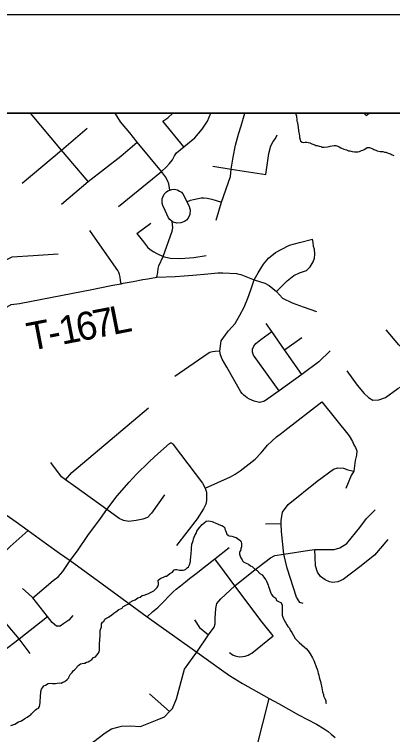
# Model space of a CAD drawing. Extents: x 0 to 34, y 0 to 22.
# Drawn here: x 7.879 to 8.261, y 20.27 to 21 of the extents above; entities that cross this region are included whole.
import ezdxf

# ---------------------------------------------------------------- set-up
doc = ezdxf.new("R2010")
doc.units = 0
for name, color, linetype in [('GM_X_Corporation', 7, 'Continuous'), ('GM_X_County_Road', 7, 'Continuous'), ('GM_X_Minor_River', 7, 'Continuous'), ('GM_X_Township_Road', 7, 'Continuous'), ('GM_X_Township_Road_Text', 7, 'Continuous'), ('SH_Cut_Line', 7, 'Continuous'), ('SH_Data', 7, 'Continuous')]:
    doc.layers.add(name, color=color, linetype=linetype)

msp = doc.modelspace()

# ---------------------------------------------------------------- linework, layer by layer
at = {"layer": 'GM_X_Corporation'}
msp.add_lwpolyline([(8.26616, 20.9), (5.67696, 20.9)], dxfattribs=at)
at = {"layer": 'GM_X_County_Road'}
msp.add_lwpolyline([(7.85884, 20.50097), (7.88029, 20.48584), (7.89246, 20.47726), (7.9113, 20.46371), (7.92425, 20.45427), (7.93502, 20.44671), (7.9675, 20.42329), (8.01317, 20.38987), (8.02704, 20.37972), (8.04097, 20.3698), (8.06328, 20.35377), (8.07499, 20.34548), (8.08822, 20.33608), (8.09625, 20.33039), (8.10945, 20.3222), (8.13664, 20.30712), (8.14579, 20.30199), (8.16632, 20.29058), (8.18434, 20.28088), (8.19201, 20.27643), (8.1961, 20.27351), (8.1994, 20.27098), (8.20326, 20.26735)], dxfattribs=at)
at = {"layer": 'GM_X_Minor_River'}
for points in [[(8.16322, 20.9), (8.16404, 20.89707), (8.16401, 20.89593), (8.16453, 20.89383), (8.16448, 20.89193), (8.16501, 20.8904), (8.1655, 20.88736), (8.16584, 20.88564), (8.16632, 20.88221), (8.16666, 20.8805), (8.16681, 20.87916), (8.16713, 20.87669), (8.16728, 20.87517), (8.16779, 20.87307), (8.16814, 20.87173), (8.16982, 20.87055), (8.17152, 20.87032), (8.17286, 20.87047), (8.17476, 20.87061), (8.17589, 20.87039), (8.17778, 20.86977), (8.17984, 20.86896), (8.18266, 20.86775), (8.18379, 20.86734), (8.18512, 20.86712), (8.187, 20.8665), (8.18908, 20.86606), (8.19021, 20.86566), (8.1921, 20.86542), (8.19553, 20.8659), (8.19706, 20.86624), (8.1982, 20.8664), (8.20011, 20.86691), (8.20221, 20.86724), (8.20411, 20.86719), (8.20599, 20.86657), (8.20749, 20.86577), (8.20898, 20.86479), (8.21218, 20.86356), (8.21482, 20.86274), (8.2167, 20.86193), (8.21802, 20.8617), (8.22066, 20.86107), (8.22294, 20.86082), (8.22522, 20.86076), (8.22636, 20.86092), (8.22789, 20.86126), (8.2298, 20.86197), (8.23115, 20.8625), (8.23249, 20.86322), (8.23423, 20.86413), (8.23577, 20.86503), (8.23691, 20.86519), (8.23805, 20.86516), (8.24143, 20.86375), (8.24256, 20.86315), (8.24444, 20.86234), (8.24594, 20.86192), (8.24897, 20.86127), (8.25029, 20.86105), (8.25143, 20.86102), (8.25332, 20.86059), (8.25445, 20.86037), (8.2569, 20.85955), (8.25916, 20.85892), (8.26028, 20.85813), (8.26253, 20.85694)], [(7.97395, 20.38953), (7.97742, 20.39172), (7.97936, 20.39337), (7.98148, 20.39464), (7.98421, 20.39723), (7.98766, 20.39866), (7.98826, 20.39978), (7.99154, 20.40159), (7.995, 20.4034), (7.99579, 20.40451), (7.99887, 20.40633), (8.00079, 20.40704), (8.0035, 20.40905), (8.0058, 20.40975), (8.00792, 20.41121), (8.01002, 20.41173), (8.01271, 20.41279), (8.01386, 20.41314), (8.01847, 20.4153), (8.01963, 20.41603), (8.02196, 20.41805), (8.02313, 20.41935), (8.02373, 20.42047), (8.02454, 20.42254), (8.02458, 20.42405), (8.02424, 20.42577), (8.02427, 20.42691), (8.02698, 20.42892), (8.02967, 20.42999), (8.03159, 20.43089), (8.03273, 20.43105), (8.0339, 20.43197), (8.03603, 20.43362), (8.03853, 20.43488), (8.04049, 20.43729), (8.04183, 20.43764), (8.04297, 20.43761), (8.04448, 20.43738), (8.0458, 20.43716), (8.04751, 20.43692), (8.04959, 20.43687), (8.05094, 20.4374), (8.0521, 20.43813), (8.05365, 20.43942), (8.055, 20.44033), (8.056, 20.44239), (8.05685, 20.44578), (8.05691, 20.44824), (8.05714, 20.44995), (8.05745, 20.45449), (8.0579, 20.45713), (8.05795, 20.45903), (8.05824, 20.46319), (8.05947, 20.46677), (8.0599, 20.46884), (8.06113, 20.47222), (8.0629, 20.47483), (8.06313, 20.47634), (8.06491, 20.47895), (8.06646, 20.48043), (8.06863, 20.48341), (8.07037, 20.4845), (8.0727, 20.48652), (8.07556, 20.48702), (8.07726, 20.48679), (8.07877, 20.48637), (8.08027, 20.48557), (8.08177, 20.48496), (8.08497, 20.48355), (8.08741, 20.48273), (8.08854, 20.48213), (8.09041, 20.48113), (8.09152, 20.47977), (8.09167, 20.47844), (8.09221, 20.4771), (8.09311, 20.47537), (8.09363, 20.47346), (8.09493, 20.47229), (8.09606, 20.47188), (8.09871, 20.47143), (8.10173, 20.47059), (8.10304, 20.46999), (8.10566, 20.46821), (8.10752, 20.46703), (8.10824, 20.4653), (8.10859, 20.46397), (8.1085, 20.46074), (8.10789, 20.45886), (8.10767, 20.45773), (8.10687, 20.45604), (8.10646, 20.45492), (8.1066, 20.45321), (8.10713, 20.4513), (8.10784, 20.44957), (8.10931, 20.44744), (8.10966, 20.4463), (8.11096, 20.44513), (8.11264, 20.44432), (8.11377, 20.44373), (8.11565, 20.44292), (8.1177, 20.44154)], [(8.1177, 20.44154), (8.1192, 20.44074), (8.12198, 20.43801), (8.12422, 20.43662), (8.127, 20.43371), (8.12943, 20.43231), (8.13162, 20.42884), (8.13329, 20.42709), (8.13382, 20.42575), (8.13472, 20.42364), (8.13543, 20.42192), (8.13597, 20.42038), (8.13649, 20.41866), (8.13701, 20.41675), (8.13772, 20.41484), (8.13826, 20.41369), (8.1388, 20.41234), (8.14009, 20.41079), (8.14326, 20.40862), (8.14378, 20.40633), (8.14659, 20.40493), (8.14847, 20.40413), (8.14955, 20.40201), (8.14968, 20.39954), (8.1495, 20.39253), (8.14966, 20.39139), (8.15037, 20.38947), (8.15126, 20.38717), (8.15235, 20.38506), (8.15289, 20.38391), (8.15436, 20.38178), (8.15526, 20.37986), (8.15692, 20.37811), (8.15763, 20.3762), (8.15928, 20.37388), (8.16129, 20.37079), (8.16273, 20.36772), (8.16422, 20.36635), (8.16681, 20.36382), (8.16941, 20.36147), (8.1722, 20.35894), (8.17388, 20.35775), (8.1761, 20.35542), (8.17811, 20.35233), (8.18028, 20.34829), (8.18173, 20.34541), (8.18226, 20.34369), (8.18404, 20.33909), (8.18512, 20.33679), (8.18547, 20.33564), (8.18581, 20.33392), (8.18615, 20.33259), (8.18667, 20.33068), (8.18719, 20.32858), (8.18789, 20.32628), (8.1886, 20.32437), (8.18894, 20.32265), (8.18943, 20.31961), (8.18995, 20.3177), (8.19062, 20.31388), (8.1915, 20.31121), (8.19165, 20.30968), (8.19254, 20.30757), (8.19308, 20.30623), (8.1938, 20.30451), (8.19395, 20.30299), (8.1943, 20.30184)], [(7.87506, 20.27965), (7.87909, 20.28106), (7.88295, 20.28342), (7.88582, 20.28449), (7.88911, 20.28686), (7.89161, 20.28794), (7.89393, 20.28977), (7.89528, 20.2905), (7.89607, 20.29161), (7.89783, 20.29365), (7.89996, 20.2955), (7.90132, 20.2966), (7.90305, 20.29731), (7.90423, 20.29899), (7.9049, 20.30276), (7.90508, 20.31015), (7.90533, 20.31242), (7.90537, 20.31394), (7.906, 20.31639), (7.90718, 20.31788), (7.90856, 20.31974), (7.91029, 20.32064), (7.91298, 20.32209), (7.91565, 20.3224), (7.91736, 20.32235), (7.91888, 20.32231), (7.92039, 20.32227), (7.92211, 20.32242), (7.92477, 20.32273), (7.9261, 20.32269), (7.92783, 20.3234), (7.92975, 20.3243), (7.93208, 20.32633), (7.93364, 20.32799), (7.93424, 20.32912), (7.93524, 20.33118), (7.93701, 20.33341), (7.938, 20.3349), (7.93936, 20.33619), (7.94169, 20.33841), (7.94268, 20.3399), (7.94423, 20.34118), (7.9454, 20.3421), (7.94883, 20.34277), (7.94998, 20.34293), (7.9517, 20.34364), (7.95323, 20.34398), (7.95497, 20.34527), (7.9569, 20.34635), (7.95866, 20.34839), (7.96058, 20.34929), (7.96214, 20.35077), (7.96351, 20.35244), (7.96431, 20.35413), (7.96474, 20.35582), (7.96492, 20.36321), (7.96517, 20.36548), (7.96533, 20.37174), (7.96556, 20.37325), (7.96563, 20.3759), (7.96667, 20.37967), (7.96693, 20.38251), (7.96793, 20.38419), (7.96909, 20.38511), (7.97009, 20.38736), (7.97125, 20.38808), (7.97395, 20.38953)]]:
    msp.add_lwpolyline(points, dxfattribs=at)
at = {"layer": 'GM_X_Township_Road'}
for p, q in [((8.0795, 20.84637), (8.09818, 20.84307)), ((7.98401, 20.80553), (8.02748, 20.84078)), ((8.00246, 20.77816), (8.01658, 20.7885)), ((8.15211, 20.66022), (8.16966, 20.67257)), ((8.14873, 20.48395), (8.13283, 20.48363)), ((8.06328, 20.35377), (8.07511, 20.37135)), ((8.03569, 20.29383), (8.01536, 20.31182))]:
    msp.add_line(p, q, dxfattribs=at)
for points in [[(7.95336, 20.83056), (7.92618, 20.86248), (7.89502, 20.9)], [(8.03581, 20.82201), (8.03508, 20.82824), (8.03407, 20.83108), (8.03169, 20.83529), (8.02748, 20.84078), (8.00299, 20.87058), (7.99543, 20.88016), (7.98596, 20.89118), (7.98067, 20.9)], [(8.02748, 20.84078), (8.03248, 20.84543), (8.03573, 20.849), (8.03855, 20.8528), (8.04061, 20.8567), (8.04288, 20.85963), (8.05004, 20.8657), (8.06131, 20.87513), (8.0688, 20.88359), (8.074, 20.89172), (8.0776, 20.9)], [(8.05004, 20.8657), (8.02901, 20.89172), (8.03378, 20.89519), (8.03914, 20.9)], [(8.08289, 20.79165), (8.08831, 20.80981), (8.0972, 20.83594), (8.09818, 20.84307), (8.10023, 20.85551), (8.1024, 20.86765), (8.10555, 20.8786), (8.10815, 20.88717), (8.11201, 20.9)], [(8.23246, 20.9), (8.23457, 20.89773), (8.2376, 20.9)], [(7.88655, 20.8289), (7.92618, 20.86248), (7.95241, 20.88472)], [(8.09818, 20.84307), (8.13297, 20.83776), (8.13627, 20.85901), (8.1381, 20.8667), (8.14067, 20.87128), (8.14287, 20.87439), (8.1447, 20.87806)], [(7.92623, 20.80789), (7.95336, 20.83056), (7.98627, 20.85654), (8.00299, 20.87058)], [(8.03581, 20.82201), (8.03801, 20.82278), (8.04067, 20.82303), (8.0433, 20.82239), (8.04409, 20.82208), (8.0459, 20.8211), (8.0479, 20.81983), (8.04921, 20.81823), (8.05041, 20.81602), (8.05334, 20.81005), (8.05522, 20.80629), (8.05652, 20.80187), (8.05622, 20.79738), (8.05447, 20.79365), (8.05274, 20.79163), (8.05086, 20.79026), (8.04717, 20.78876), (8.04319, 20.78846), (8.04211, 20.78878), (8.04051, 20.78921), (8.0382, 20.79036), (8.03612, 20.79219), (8.03469, 20.79391), (8.03125, 20.80126), (8.02887, 20.80655), (8.02827, 20.80886), (8.02814, 20.81111), (8.02837, 20.81316), (8.02879, 20.81485), (8.0303, 20.81781), (8.03172, 20.81941), (8.03271, 20.82036), (8.03411, 20.8213), (8.03581, 20.82201)], [(8.05334, 20.81005), (8.05692, 20.81166), (8.05985, 20.81252), (8.06451, 20.81366), (8.0676, 20.81421), (8.07053, 20.81421), (8.07389, 20.81399), (8.07834, 20.81279), (8.08273, 20.81149), (8.08831, 20.80981)], [(8.02296, 20.73368), (8.02373, 20.73859), (8.02409, 20.74262), (8.02473, 20.74518), (8.02914, 20.75462), (8.03847, 20.78035), (8.03902, 20.78364), (8.0382, 20.79036)], [(7.9867, 20.72721), (7.98615, 20.73036), (7.98566, 20.73374), (7.98508, 20.73637), (7.98434, 20.7385), (7.98327, 20.74064), (7.98171, 20.74286), (7.95516, 20.78117)], [(8.00246, 20.77816), (8.00944, 20.76945), (8.01329, 20.76432), (8.01622, 20.76176), (8.0197, 20.75956), (8.02281, 20.75791), (8.02914, 20.75462)], [(8.19824, 20.65921), (8.18667, 20.6479), (8.16963, 20.63522), (8.14669, 20.6185), (8.13191, 20.60828), (8.12665, 20.60694), (8.12131, 20.60828), (8.11658, 20.61025), (8.11417, 20.61149), (8.11245, 20.61278), (8.11072, 20.61424), (8.10909, 20.61599), (8.10792, 20.61777), (8.09371, 20.64278), (8.09118, 20.64657), (8.08893, 20.65079), (8.08724, 20.65529), (8.08668, 20.65894), (8.0878, 20.66935), (8.09244, 20.67525), (8.09548, 20.67929), (8.102, 20.68703), (8.10688, 20.69517), (8.1112, 20.70336), (8.11494, 20.7127), (8.1181, 20.72111), (8.12144, 20.73125), (8.12521, 20.73834), (8.13071, 20.7469), (8.1358, 20.75321), (8.14293, 20.75871), (8.14863, 20.76196), (8.15698, 20.76624), (8.16716, 20.76909), (8.1804, 20.77215)], [(8.14377, 20.71933), (8.15474, 20.7302), (8.16146, 20.73549), (8.16726, 20.73804), (8.17419, 20.74058), (8.17805, 20.74445), (8.18091, 20.74934), (8.18253, 20.753), (8.18284, 20.75708), (8.18223, 20.76217), (8.18152, 20.76502), (8.18101, 20.76889), (8.1804, 20.77215)], [(7.73837, 20.75876), (7.74709, 20.74578), (7.75642, 20.73231), (7.76682, 20.7186), (7.7753, 20.70749), (7.77741, 20.70421), (7.78757, 20.70542), (7.81644, 20.72104), (7.833, 20.73134), (7.8476, 20.73881), (7.84888, 20.73959), (7.85976, 20.74627), (7.86837, 20.75043), (7.87655, 20.75438), (7.8975, 20.75587), (7.92283, 20.75738)], [(8.02914, 20.75462), (8.03627, 20.75297), (8.04671, 20.75278), (8.06017, 20.7537), (8.07263, 20.7559)], [(8.01375, 20.73223), (8.02296, 20.73368), (8.0415, 20.73463), (8.05057, 20.73508), (8.0592, 20.73592), (8.07446, 20.73708), (8.08456, 20.73832), (8.08967, 20.7381), (8.10342, 20.73739), (8.10432, 20.7372)], [(8.10432, 20.7372), (8.10791, 20.73646), (8.12144, 20.73125), (8.13202, 20.72765), (8.13647, 20.72533), (8.14377, 20.71933), (8.14985, 20.71268), (8.15962, 20.7078), (8.17082, 20.70371), (8.18452, 20.69918)], [(7.95876, 20.72169), (7.96339, 20.72258), (7.97831, 20.72566), (7.9867, 20.72721), (7.98886, 20.72761), (7.99892, 20.72956), (8.00868, 20.73143), (8.01375, 20.73223)], [(7.74011, 20.62899), (7.75201, 20.63383), (7.75966, 20.63921), (7.76825, 20.64402), (7.77494, 20.6479), (7.78506, 20.65343), (7.84094, 20.68651), (7.85295, 20.69325), (7.87539, 20.70607), (7.88375, 20.70728), (7.95876, 20.72169)], [(8.16963, 20.63522), (8.15211, 20.66022), (8.13918, 20.67868), (8.13336, 20.68699)], [(8.14669, 20.6185), (8.12072, 20.65496), (8.11957, 20.65771), (8.11974, 20.66101), (8.12099, 20.66377), (8.12295, 20.66652), (8.1282, 20.67053), (8.13918, 20.67868)], [(8.33975, 20.59916), (8.3352, 20.60574), (8.32532, 20.61811), (8.31633, 20.63039), (8.31288, 20.63465), (8.30986, 20.63854), (8.30399, 20.64619), (8.29817, 20.64881), (8.29165, 20.65125), (8.28688, 20.65276), (8.2806, 20.65602), (8.27525, 20.65846), (8.27083, 20.66195), (8.26758, 20.66521), (8.25501, 20.68033)], [(8.08668, 20.65894), (8.08192, 20.65864), (8.07924, 20.65829), (8.07632, 20.65747), (8.07466, 20.65663), (8.041, 20.6332)], [(8.21515, 20.63895), (8.2256, 20.62436), (8.23276, 20.61611), (8.23689, 20.61198), (8.24129, 20.60922), (8.24751, 20.60949), (8.25427, 20.6118), (8.26655, 20.62106), (8.27128, 20.62381), (8.27569, 20.62794), (8.27897, 20.63298)], [(8.07187, 20.52014), (8.09741, 20.53166), (8.102, 20.53426), (8.10698, 20.53747), (8.12228, 20.54942), (8.1283, 20.55586), (8.13168, 20.55983), (8.13474, 20.56354), (8.13907, 20.56781), (8.14388, 20.57192), (8.14895, 20.57586), (8.15241, 20.57838), (8.18972, 20.60753), (8.21731, 20.57325), (8.22077, 20.56736), (8.22212, 20.56381), (8.22389, 20.56113), (8.22514, 20.55782), (8.22496, 20.55334), (8.22362, 20.54797), (8.22233, 20.5373), (8.21951, 20.53293), (8.21413, 20.51977)], [(7.93054, 20.5286), (7.93664, 20.536), (8.01431, 20.60131)], [(7.89721, 20.40909), (7.918, 20.4264), (7.92289, 20.43016), (7.92766, 20.43573), (7.93502, 20.44671), (7.94257, 20.45666), (7.95315, 20.47202), (7.96565, 20.4892), (7.97214, 20.49836), (7.98282, 20.51215), (7.99472, 20.52625), (8.0023, 20.53431), (8.01476, 20.5465), (8.02092, 20.552), (8.03567, 20.56528), (8.0362, 20.56567), (8.03659, 20.56594), (8.03712, 20.56606), (8.03759, 20.56594), (8.03793, 20.56582), (8.03849, 20.56538), (8.03892, 20.5649), (8.03921, 20.56446), (8.06895, 20.525), (8.07187, 20.52014), (8.07323, 20.51587), (8.07323, 20.5115), (8.07313, 20.50762), (8.07245, 20.50393), (8.07012, 20.49917), (8.06352, 20.48908), (8.0428, 20.46185)], [(8.03049, 20.51342), (8.01733, 20.49482), (8.01325, 20.49045), (8.00855, 20.48876), (8.00187, 20.4873), (7.99435, 20.48646), (7.98892, 20.4873), (7.98453, 20.48918), (7.97214, 20.49836), (7.941, 20.52105), (7.93054, 20.5286), (7.92623, 20.53164), (7.91546, 20.54597)], [(8.17101, 20.40338), (8.1675, 20.40438), (8.16429, 20.4097), (8.15476, 20.4391), (8.1513, 20.45332), (8.14894, 20.47603), (8.14873, 20.48395), (8.14873, 20.48717), (8.14992, 20.49564), (8.15556, 20.50342), (8.18506, 20.5273), (8.20151, 20.53934), (8.20613, 20.54075), (8.21188, 20.54031), (8.21617, 20.53874), (8.22233, 20.5373)], [(8.07511, 20.37135), (8.08067, 20.3791), (8.08173, 20.38263), (8.08191, 20.38854), (8.08263, 20.3982), (8.0837, 20.4034), (8.08746, 20.40805), (8.1016, 20.42112), (8.12058, 20.43634), (8.13777, 20.44941), (8.14234, 20.45183), (8.1513, 20.45332), (8.1772, 20.45712), (8.18274, 20.45798), (8.20223, 20.45782), (8.20787, 20.45952), (8.21512, 20.46409), (8.22837, 20.48038), (8.23499, 20.48942), (8.24368, 20.49802)], [(7.82492, 20.41506), (7.82872, 20.41827), (7.86009, 20.44748), (7.87453, 20.46087), (7.89246, 20.47726)], [(8.25663, 20.46811), (8.24325, 20.45223), (8.22821, 20.44024), (8.21135, 20.4277), (8.20591, 20.42505), (8.20103, 20.42436), (8.19741, 20.42533), (8.19323, 20.42728), (8.18835, 20.43063), (8.18529, 20.43481), (8.18334, 20.4415), (8.18292, 20.45), (8.18274, 20.45798)], [(8.01317, 20.38987), (8.0187, 20.39502), (8.02168, 20.39759), (8.02425, 20.39964), (8.02733, 20.40262), (8.03083, 20.40632), (8.03411, 20.40971), (8.03925, 20.41495), (8.04244, 20.41783), (8.04665, 20.42112), (8.05179, 20.42533), (8.056, 20.42862), (8.06258, 20.43355), (8.07059, 20.43992), (8.08148, 20.44855), (8.09607, 20.45996)], [(8.09634, 20.35368), (8.09993, 20.35087), (8.10207, 20.35009), (8.10468, 20.3495), (8.10664, 20.34931), (8.1097, 20.34942), (8.11234, 20.34991), (8.1152, 20.35092), (8.11703, 20.35185), (8.11888, 20.35308), (8.14046, 20.37054), (8.12944, 20.38416), (8.1016, 20.42112), (8.09122, 20.43518), (8.08148, 20.44855)], [(7.93779, 20.39091), (7.93381, 20.38625), (7.92857, 20.38283), (7.92494, 20.38033), (7.92129, 20.38033), (7.91697, 20.38397), (7.91215, 20.3901), (7.89721, 20.40909), (7.89274, 20.4132), (7.88671, 20.41844)], [(7.89468, 20.35246), (7.88353, 20.36747), (7.861, 20.39387)], [(7.82642, 20.30445), (7.83195, 20.311), (7.83431, 20.31483), (7.83931, 20.32772), (7.84083, 20.33054), (7.84219, 20.33239), (7.84402, 20.33421), (7.85507, 20.34404), (7.8676, 20.35543), (7.88353, 20.36747), (7.91215, 20.3901)], [(8.06087, 20.38657), (8.06597, 20.37895), (8.07511, 20.37135)], [(7.88924, 20.18401), (7.89677, 20.19383), (7.9327, 20.2349), (7.95254, 20.25412), (7.95902, 20.26353), (7.97051, 20.27209), (7.97677, 20.27627), (7.98701, 20.27899), (7.99599, 20.27941), (8.00644, 20.27857), (8.02315, 20.28526), (8.03067, 20.28839), (8.03569, 20.29383), (8.03861, 20.29696), (8.04258, 20.30678), (8.05075, 20.33676), (8.05962, 20.34882), (8.06328, 20.35377)], [(8.09624, 20.19841), (8.10328, 20.20398), (8.10729, 20.20727), (8.11158, 20.21171), (8.11358, 20.21915), (8.11716, 20.23088), (8.13664, 20.30712)]]:
    msp.add_lwpolyline(points, dxfattribs=at)
at = {"layer": 'SH_Cut_Line'}
msp.add_lwpolyline([(8.9, 14.1), (8.9, 20.9), (5.67696, 20.9)], dxfattribs=at)
at = {"layer": 'SH_Data'}
for p, q in [((2, 21), (9, 21)), ((2.1, 20.9), (8.9, 20.9))]:
    msp.add_line(p, q, dxfattribs=at)

# ---------------------------------------------------------------- texts
at = {"layer": 'GM_X_Township_Road_Text'}
for s, rotation, p in [('6', 10.91841, (7.94388, 20.66862)), ('7', 10.94708, (7.96108, 20.67194)), ('L', 11.11673, (7.97835, 20.67528)), ('T', 10.90819, (7.89437, 20.65907)), ('1', 10.91402, (7.92669, 20.6653)), ('-', 10.90786, (7.91523, 20.6631))]:
    msp.add_text(s, height=0.02841, rotation=rotation, dxfattribs=at).set_placement(p)

doc.saveas('drawing.dxf')
